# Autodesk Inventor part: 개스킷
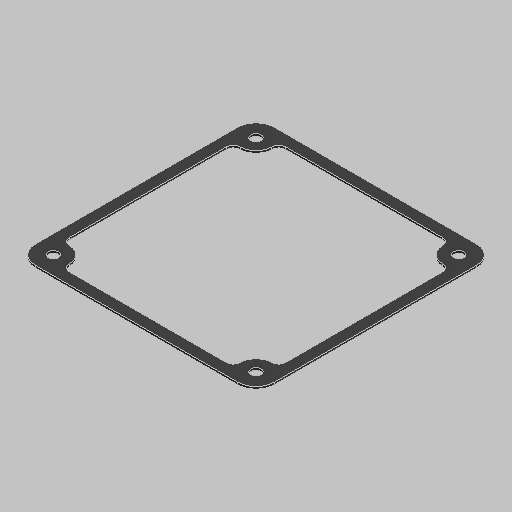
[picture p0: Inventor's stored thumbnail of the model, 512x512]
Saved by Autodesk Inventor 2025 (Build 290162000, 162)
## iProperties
Created: 2024-08
Part Number: 개스킷
Material: 고무
Document SubType Name: Modeling
Designer: 현기
Density: 0.93 g/cm^3
Appearance: 기본값
Author: jhkim
Sending System: Autodesk Inventor 2025
Preprocessor: ST-DEVELOPER v20
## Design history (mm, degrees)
feature "솔리드1"
node "솔리드2"
